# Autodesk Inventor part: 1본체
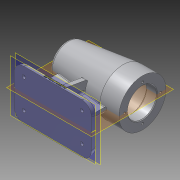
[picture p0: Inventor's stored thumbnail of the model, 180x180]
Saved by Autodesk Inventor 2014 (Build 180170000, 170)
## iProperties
Created: 2017-01
Part Number: 1본체
Material: 알루미늄 6061
Document SubType Name: Modeling
Designer: owner
Density: 2.71 g/cm^3
Appearance: 알루미늄 - 평지
Mass: 672.64 g
Surface Area: 671.875 cm^2
Volume: 248.207 cm^3
Author: owner
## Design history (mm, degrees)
sketch "스케치1"
  geometry: L1 (0, 0)-(112, 0); L2 (6, 0)-(6, 10.5); L3 (6, 10.5)-(9, 10.5); L4 (9, 10.5)-(9, 16); L5 (9, 16)-(13, 16); L6 (13, 16)-(13, 17.5); L7 (13, 17.5)-(31, 17.5); L8 (31, 17.5)-(31, 21); L9 (97, 24)-(97, 21); L10 (112, 12.806)-(112, 0); L11 (97, 21)-(112, 21); L12 (3.73, 24.144)-(84, 34); L13 (84, 34)-(112, 34); L14 (31, 21)-(43, 21); L15 (43, 21)-(43, 24); L16 (43, 24)-(97, 24); L17 (112, 34)-(112, 21); A1 r 80 centre (80, 0) between (3.73, 24.144) and (0, 0); 1 further point
  constraints: 34 end point, 8 perpendicular, 5 parallel, 2 point on circle, 2 point on line, 1 centre point, 1 coincident, 1 horizontal, 1 vertical alignment
  dimensions: "d0" = 112 distance of L1.start L1.end; "d12" = 7 deg angle of L12 L13; "d13" = 28 distance of L12.end L13.end; "d18" = 68 diameter of L13.end L1; "d22" = 42 diameter of L11 L1; "d23" = 15 distance of L9.end L11.end; "d24" = 54 distance of L15.end L9.start; "d25" = 12 distance of L8.end L14.end; "d26" = 3 distance of L2.end L3.end; "d27" = 4 distance of L4.end L5.end; "d28" = 18 distance of L6.end L7.end; "d29" = 48 diameter of L16 L1; "d30" = 42 diameter of L14 L1; "d31" = 35 diameter of L7 L1; "d32" = 32 diameter of L5 L1; "d33" = 21 diameter of L3 L1; "d34" = 80 radius of A1
revolve "회전1" sketch "스케치1" stored, may be unused: angle "d35" = 90 deg
node "작업 평면1"
sketch "스케치2"
  geometry: L1 (-112, 34)-(0, 34); L2 (0, 34)-(0, -36); L3 (0, -36)-(-112, -36); L4 (-112, -36)-(-112, 34); L5 (-84, 34)-(-112, 34) reference; L6 (-112, 34)-(-112, -34) reference; 1 further point
  constraints: 8 end point, 2 coincident, 2 parallel, 1 horizontal, 1 perpendicular
  dimensions: "d37" = 112 distance of L1.start L1.end; "d38" = 70 distance of L1.end L2.end
extrude "돌출1" join sketch "스케치2" distance "d39" = 7; taper "d40" = 0 deg
feature "면 기울기1" dims angle "d55" = -15 deg
sketch "스케치6"
  geometry: L1 (112, -67)-(0, -67) reference; L2 (3.73, -24.144)-(84, -34) reference; L3 (84, -34)-(112, -34) reference; L4 (94, -67)-(94, -34); L5 (56, -30.562)-(56, -67); L6 (0, -67)-(112, -67) reference; 3 further points
  constraints: 4 end point, 3 midpoint, 3 point on line, 2 perpendicular, 1 vertical alignment
  dimensions: "d58" = 18 distance from line of L4 L1.start
extrude "돌출3" join sketch "스케치6" stored distance "d60" = 8; taper "d61" = 0 deg
node "작업 평면2"
sketch "스케치8"
  geometry: L1 (-30.562, 0)-(-34, 0) reference; L2 (-67, -36)-(-67, 32.124) reference; L3 (-25.596, -16.699)-(-67, -24); L4 (-30.562, 0)-(-67, 0); C1 r 24.144 at (0, 0) reference; A1 r 30.562 centre (0, 0) between (-30.562, 0) and (-25.596, -16.699); 2 further points
  constraints: 4 end point, 2 point on circle, 2 point on line, 1 centre point, 1 coincident, 1 horizontal alignment, 1 perpendicular
  dimensions: "d66" = 12 distance of L3.end L2.start; "d67" = 100 deg angle of L3 L2
extrude "돌출5" join sketch "스케치8" stored distance "d69" = 8; taper "d70" = 0 deg
sketch "스케치10"
  geometry: L1 (3.73, -24.144)-(84, -34) reference; L2 (112, -67)-(0, -67) reference; L3 (18, -25.896)-(18, -67); L4 (0, -74)-(0, -67) reference; L5 (52, -25.596)-(52, -67) reference; L6 (18, -67)-(52, -67); L7 (52, -30.071)-(18, -25.896); 1 further point
  constraints: 6 end point, 4 point on line, 2 collinear, 1 perpendicular
  dimensions: "d71" = 18 distance between parallel lines of L3 L4
extrude "돌출6" join sketch "스케치10" stored distance "d72" = 8; taper "d73" = 0 deg
fillet "모깎기2" dims "d74" = 14
fillet "모깎기3" dims "d75" = 14
sketch "스케치11" dims "d76" = 10
  geometry: L1 (16.887, 26.506)-(19.774, 21.506); L2 (19.774, 21.506)-(16.887, 16.506); L3 (16.887, 16.506)-(11.113, 16.506); L4 (11.113, 16.506)-(8.226, 21.506); L5 (8.226, 21.506)-(11.113, 26.506); L6 (11.113, 26.506)-(16.887, 26.506); 7 further points; 1 other entity
  constraints: 12 end point, 2 coincident, 1 midpoint, 1 vertical alignment, 16 other
  dimensions: "d106" = 5 vertical distance of L1.start L1.end
fillet "모깎기4" dims "d79" = 1
sketch "스케치12"
  geometry: C1 r 34 at (0, 0) reference; 1 further point
  constraints: 1 vertical alignment
  dimensions: "d95" = 26 distance of point (0, 26) C1.centre
hole "구멍2" sketch "스케치12" at (0, 26) diameter "d96" = 3.242; stored, may be unused: countersink angle "d100" = 90 deg, drill point angle "d102" = 118 deg; dims "d97" = 8, "d98" = 4, "d99" = 2, "d101" = 11
extrude "돌출8" cut sketch "스케치11" distance "d107" = 4; taper "d108" = 0 deg
sketch "스케치14"
  geometry: L1 (11.113, 26.506)-(16.887, 26.506) reference; C1 r 2.5 at (14, 21.506); 3 further points
  constraints: 1 centre point, 1 horizontal alignment, 1 midpoint, 1 vertical alignment
  dimensions: "d112" = 5 diameter of C1
extrude "돌출10" cut sketch "스케치14" stored distance "d113" = 4; taper "d114" = 0 deg
fillet "모깎기5" dims "d121" = 0.3
chamfer "모따기1" distance "d123" = 1; stored, may be unused: second distance "d124" = 2, angle "d125" = 45 deg
fillet "모깎기7" dims "d126" = 3
fillet "모깎기8" dims "d127" = 3
fillet "모깎기9" dims "d128" = 3
fillet "모깎기10" dims "d129" = 3
fillet "모깎기11" dims "d130" = 3
fillet "모깎기12" dims "d131" = 3
fillet "모깎기13" dims "d135" = 2
fillet "모깎기14" dims "d136" = 2
sketch "스케치15"
  geometry: L1 (84, 0)-(0, 0) reference; L2 (98, 3.751)-(98, 9.963) reference; 2 further points
  constraints: 1 other
  dimensions: "d137" = 56 distance from line of point (42, 4) L2; "d138" = 4 distance from line of point (42, 4) L1
feature "엠보싱1" sketch "스케치15" dims "d139" = 0.5, "d140" = 0
fillet "모깎기15" dims "d141" = 3
fillet "모깎기16" dims "d142" = 3
node "작업 평면4"
node "작업 평면5"
sketch "스케치16"
  geometry: L1 (0, -68)-(0, -74) reference; L2 (112, -74)-(112, -68) reference; 1 further point
fillet "모깎기17" dims "d144" = 3
node "솔리드1"
mirror "대칭1"
pattern_linear "직사각형 패턴2" dims "d117" = 42, "d120" = 84
pattern_circular "원형 패턴2" dims angle "d133" = 360 deg
node "투영된 루프2"
node "작업 평면3"
other parameters: "d36" = -74, "d143" = 90 deg
